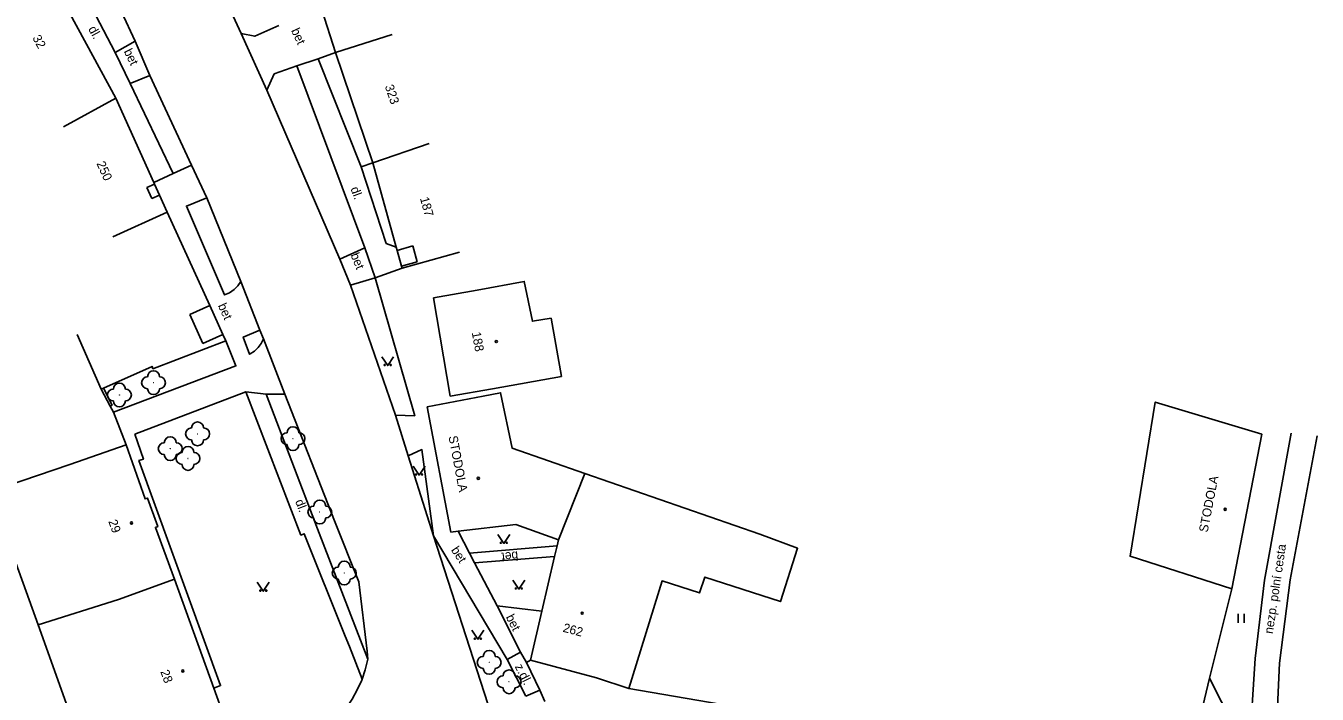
# Model space of a CAD drawing. Extents: x -544674 to -541478, y -1199076 to -1195527.
# Drawn here: x -542552 to -542443.8, y -1198856.1 to -1198800 of the extents above; entities that cross this region are included whole.
import ezdxf

# ---------------------------------------------------------------- set-up
doc = ezdxf.new("R2010")
doc.units = 0
for name, color, linetype in [('BUDOVY_MĚŘ', 7, 'Continuous'), ('BUDOVY_NEMĚŘ', 7, 'Continuous'), ('POMOC_POPIS', 7, 'Continuous'), ('ROZHRANÍ_PLOCH', 7, 'Continuous'), ('ZELEŇ', 7, 'Continuous'), ('ZN_BUDOV', 7, 'Continuous'), ('ZN_DOPLŇKOVÉ', 7, 'Continuous'), ('ZN_KULTUR', 7, 'Continuous'), ('Č_POPIS_ORIENT', 7, 'Continuous')]:
    doc.layers.add(name, color=color, linetype=linetype)

msp = doc.modelspace()

# ---------------------------------------------------------------- linework, layer by layer
at = {"layer": 'BUDOVY_MĚŘ'}
for points in [[(-542548.34, -1198798.99), (-542544.49, -1198806.08)], [(-542527.22, -1198798.68), (-542526.08, -1198802.26)], [(-542521.31, -1198800.74), (-542526.08, -1198802.26)], [(-542526.08, -1198802.26), (-542522.94, -1198811.5)], [(-542548.88, -1198808.47), (-542544.49, -1198806.08)], [(-542544.49, -1198806.08), (-542541.3, -1198813.16)], [(-542518.21, -1198809.89), (-542522.94, -1198811.5)], [(-542522.94, -1198811.5), (-542520.98, -1198818.56)], [(-542541.3, -1198813.16), (-542541.24, -1198813.29)], [(-542541.24, -1198813.29), (-542540.83, -1198814.2)], [(-542540.83, -1198814.2), (-542540.18, -1198815.64)], [(-542544.74, -1198817.7), (-542540.18, -1198815.64)], [(-542540.18, -1198815.64), (-542536.62, -1198823.47)], [(-542520.98, -1198818.56), (-542520.9, -1198818.84)], [(-542520.9, -1198818.84), (-542520.53, -1198820.17)], [(-542520.49, -1198820.33), (-542515.67, -1198818.99)], [(-542520.53, -1198820.17), (-542520.49, -1198820.33)], [(-542514.19, -1198822.18), (-542517.87, -1198822.81)], [(-542517.87, -1198822.81), (-542516.46, -1198831.07)], [(-542536.62, -1198823.47), (-542535.52, -1198825.89)], [(-542545.71, -1198830.47), (-542547.74, -1198825.9)], [(-542535.52, -1198825.89), (-542535.28, -1198826.43)], [(-542535.28, -1198826.43), (-542541.38, -1198828.77), (-542541.45, -1198828.58), (-542545.53, -1198830.39)], [(-542545.53, -1198830.39), (-542545.71, -1198830.47)], [(-542513.68, -1198831.07), (-542518.39, -1198831.96)], [(-542516.46, -1198831.07), (-542512.91, -1198830.46)], [(-542518.39, -1198831.96), (-542516.4, -1198842.46), (-542515.79, -1198842.39)], [(-542450.93, -1198847.22), (-542448.41, -1198834.25)], [(-542548.34, -1198836.8), (-542543.62, -1198835.15)], [(-542543.62, -1198835.15), (-542542.04, -1198839.68), (-542541.85, -1198839.61), (-542540.98, -1198842), (-542541.17, -1198842.07), (-542539.58, -1198846.42)], [(-542515.79, -1198842.39), (-542510.95, -1198841.84), (-542507.38, -1198843.11)], [(-542507.38, -1198843.11), (-542507.5, -1198843.61)], [(-542507.5, -1198843.61), (-542507.71, -1198844.51)], [(-542507.71, -1198844.51), (-542508.77, -1198849.09)], [(-542544.28, -1198848.13), (-542539.58, -1198846.42)], [(-542536.28, -1198855.55), (-542539.58, -1198846.42)], [(-542508.77, -1198849.09), (-542509.73, -1198853.2)], [(-542509.73, -1198853.2), (-542504.18, -1198854.68)], [(-542504.18, -1198854.68), (-542501.47, -1198855.58)], [(-542534.53, -1198860.37), (-542536.28, -1198855.55)]]:
    msp.add_lwpolyline(points, dxfattribs=at)
at = {"layer": 'BUDOVY_NEMĚŘ'}
for points in [[(-542512.91, -1198830.46), (-542507.14, -1198829.41), (-542508, -1198824.54), (-542509.57, -1198824.78), (-542510.25, -1198821.45), (-542514.19, -1198822.18)], [(-542505.18, -1198837.54), (-542511.25, -1198835.43), (-542512.23, -1198830.78), (-542513.68, -1198831.07)], [(-542448.41, -1198834.25), (-542457.34, -1198831.56), (-542459.46, -1198844.49), (-542450.93, -1198847.22)], [(-542548.34, -1198836.8), (-542555.03, -1198839.07), (-542554.8, -1198839.73), (-542556.18, -1198840.24), (-542555.02, -1198843.47), (-542553.63, -1198842.96), (-542551.01, -1198850.23)], [(-542507.38, -1198843.11), (-542505.18, -1198837.54)], [(-542505.18, -1198837.54), (-542490.49, -1198842.65), (-542487.33, -1198843.82), (-542488.77, -1198848.29), (-542495.12, -1198846.24), (-542495.55, -1198847.57), (-542498.69, -1198846.56), (-542501.47, -1198855.58)], [(-542551.01, -1198850.23), (-542544.28, -1198848.13)], [(-542551.01, -1198850.23), (-542547.26, -1198860.73), (-542543.03, -1198859.19), (-542541.43, -1198862.87)]]:
    msp.add_lwpolyline(points, dxfattribs=at)
at = {"layer": 'ROZHRANÍ_PLOCH'}
for points in [[(-542539.99, -1198787.62), (-542533.99, -1198800.65)], [(-542547.44, -1198791.44), (-542542.86, -1198801.31)], [(-542549.71, -1198792.34), (-542544.54, -1198802.24)], [(-542533.99, -1198800.65), (-542532.84, -1198800.89), (-542530.82, -1198800)], [(-542533.99, -1198800.65), (-542531.82, -1198805.4)], [(-542544.54, -1198802.24), (-542542.86, -1198801.31)], [(-542544.54, -1198802.24), (-542543.29, -1198804.86)], [(-542542.86, -1198801.31), (-542541.63, -1198804.18)], [(-542526.08, -1198802.26), (-542527.54, -1198802.77)], [(-542527.54, -1198802.77), (-542529.32, -1198803.38)], [(-542527.54, -1198802.77), (-542523.93, -1198811.84)], [(-542543.29, -1198804.86), (-542541.63, -1198804.18)], [(-542541.63, -1198804.18), (-542538.14, -1198811.69)], [(-542529.32, -1198803.38), (-542531.21, -1198804.04), (-542531.82, -1198805.4)], [(-542523.61, -1198818.63), (-542529.32, -1198803.38)], [(-542543.29, -1198804.86), (-542539.68, -1198812.41)], [(-542531.82, -1198805.4), (-542525.71, -1198819.58)], [(-542538.14, -1198811.69), (-542539.68, -1198812.41)], [(-542538.14, -1198811.69), (-542536.86, -1198814.45)], [(-542523.93, -1198811.84), (-542522.94, -1198811.5)], [(-542523.93, -1198811.84), (-542521.82, -1198818.26), (-542520.98, -1198818.56)], [(-542539.68, -1198812.41), (-542541.3, -1198813.16)], [(-542541.88, -1198813.58), (-542541.24, -1198813.29)], [(-542541.47, -1198814.49), (-542541.88, -1198813.58)], [(-542541.47, -1198814.49), (-542540.83, -1198814.2)], [(-542536.86, -1198814.45), (-542538.58, -1198815.13), (-542535.39, -1198822.58), (-542534.96, -1198822.39), (-542534.58, -1198822.13), (-542534.26, -1198821.82), (-542534, -1198821.45)], [(-542536.86, -1198814.45), (-542534, -1198821.45)], [(-542520.9, -1198818.84), (-542519.59, -1198818.47)], [(-542519.59, -1198818.47), (-542519.22, -1198819.8)], [(-542523.61, -1198818.63), (-542525.71, -1198819.58)], [(-542525.71, -1198819.58), (-542524.81, -1198821.77)], [(-542522.74, -1198821.14), (-542523.61, -1198818.63)], [(-542520.49, -1198820.33), (-542522.74, -1198821.14)], [(-542520.53, -1198820.17), (-542519.22, -1198819.8)], [(-542534, -1198821.45), (-542532.41, -1198825.53)], [(-542524.81, -1198821.77), (-542522.74, -1198821.14)], [(-542521.03, -1198832.67), (-542519.43, -1198832.71), (-542522.74, -1198821.14)], [(-542524.81, -1198821.77), (-542521.03, -1198832.67)], [(-542538.3, -1198824.23), (-542536.62, -1198823.47)], [(-542537.2, -1198826.65), (-542538.3, -1198824.23)], [(-542537.2, -1198826.65), (-542535.52, -1198825.89)], [(-542532.41, -1198825.53), (-542533.81, -1198826.12), (-542533.28, -1198827.55), (-542533.23, -1198827.53), (-542532.87, -1198827.3), (-542532.56, -1198827), (-542532.31, -1198826.66), (-542532.12, -1198826.27)], [(-542532.41, -1198825.53), (-542532.12, -1198826.27)], [(-542535.28, -1198826.43), (-542534.43, -1198828.53), (-542544.68, -1198832.41)], [(-542532.12, -1198826.27), (-542530.31, -1198830.9)], [(-542533.58, -1198830.7), (-542542.91, -1198834.26)], [(-542533.58, -1198830.7), (-542531.88, -1198830.91)], [(-542533.58, -1198830.7), (-542528.97, -1198842.71), (-542528.69, -1198842.6), (-542525.27, -1198851.19), (-542524.89, -1198852.07), (-542523.85, -1198854.79)], [(-542530.31, -1198830.9), (-542531.88, -1198830.91)], [(-542531.88, -1198830.91), (-542527.59, -1198842.18), (-542523.36, -1198853.11)], [(-542530.31, -1198830.9), (-542526.17, -1198841.53), (-542524.12, -1198846.63)], [(-542544.68, -1198832.41), (-542544.98, -1198831.9)], [(-542521.03, -1198832.67), (-542519.99, -1198836.08)], [(-542542.91, -1198834.26), (-542542.18, -1198836.34), (-542542.56, -1198836.47), (-542535.71, -1198855.34), (-542536.28, -1198855.55)], [(-542445.96, -1198834.18), (-542448.2, -1198846.5), (-542448.97, -1198853.07), (-542449.45, -1198860.45), (-542449.85, -1198863.37), (-542450.69, -1198865.58), (-542451.64, -1198867.29), (-542453.03, -1198868.4), (-542453.67, -1198868.75), (-542455.26, -1198869.34)], [(-542449.61, -1198870.92), (-542449.06, -1198868.38), (-542447.68, -1198864.24), (-542447.25, -1198860.78), (-542446.93, -1198853.47), (-542446.03, -1198846.48), (-542443.77, -1198834.39)], [(-542519.99, -1198836.08), (-542518.83, -1198835.55), (-542517.86, -1198842.77)], [(-542519.99, -1198836.08), (-542517.86, -1198842.77)], [(-542517.86, -1198842.77), (-542513.3, -1198856.86)], [(-542517.86, -1198842.77), (-542511.68, -1198853.16)], [(-542515.79, -1198842.39), (-542514.84, -1198844.22)], [(-542507.5, -1198843.61), (-542514.84, -1198844.22)], [(-542514.84, -1198844.22), (-542514.41, -1198845.04)], [(-542507.71, -1198844.51), (-542514.41, -1198845.04)], [(-542514.41, -1198845.04), (-542512.53, -1198848.65)], [(-542524.12, -1198846.63), (-542523.43, -1198852.44)], [(-542512.53, -1198848.65), (-542510.56, -1198852.53)], [(-542512.53, -1198848.65), (-542508.77, -1198849.09)], [(-542523.36, -1198853.11), (-542523.59, -1198854.02), (-542523.85, -1198854.79)], [(-542523.43, -1198852.44), (-542523.36, -1198853.11)], [(-542510.56, -1198852.53), (-542511.68, -1198853.16)], [(-542510.56, -1198852.53), (-542510.07, -1198853.41)], [(-542511.68, -1198853.16), (-542510.13, -1198856.23)], [(-542510.07, -1198853.41), (-542509.73, -1198853.2)], [(-542508.95, -1198855.72), (-542510.07, -1198853.41)], [(-542523.85, -1198854.79), (-542523.88, -1198854.87), (-542524.25, -1198855.69), (-542524.69, -1198856.48), (-542525.19, -1198857.22), (-542525.66, -1198857.79), (-542526.81, -1198859.02), (-542528.01, -1198860.19), (-542529.27, -1198861.3), (-542530.58, -1198862.35), (-542531.94, -1198863.33), (-542532.56, -1198863.75), (-542535.73, -1198865.15)], [(-542510.13, -1198856.23), (-542508.95, -1198855.72)], [(-542508.95, -1198855.72), (-542508.52, -1198856.67)]]:
    msp.add_lwpolyline(points, dxfattribs=at)
at = {"layer": 'ZELEŇ'}
msp.add_lwpolyline([(-542455.55, -1198866.21), (-542453.49, -1198867.42), (-542451.08, -1198863.87), (-542450.79, -1198858.67), (-542452.79, -1198854.71)], dxfattribs=at)
for centre in [(-542541.33, -1198829.94), (-542544.19, -1198830.97), (-542537.64, -1198834.23), (-542529.64, -1198834.63), (-542539.93, -1198835.47), (-542538.44, -1198836.29), (-542527.39, -1198840.78), (-542525.34, -1198845.9), (-542513.19, -1198853.39), (-542511.52, -1198855.02)]:
    msp.add_circle(centre, 0.0005, dxfattribs=at)
for centre, start, end in [((-542541.33, -1198829.44), 0, 179.99999), ((-542544.19, -1198830.47), 0, 179.99999), ((-542541.83, -1198829.94), 89.99999, 269.99999), ((-542540.83, -1198829.94), 270, 89.99999), ((-542544.69, -1198830.97), 89.99999, 269.99999), ((-542544.19, -1198831.47), 179.99999, 359.99999), ((-542543.69, -1198830.97), 270, 89.99999), ((-542541.33, -1198830.44), 179.99999, 359.99999), ((-542537.64, -1198833.73), 0, 179.99999), ((-542529.64, -1198834.13), 0, 179.99999), ((-542539.93, -1198834.97), 0, 179.99999), ((-542538.14, -1198834.23), 89.99999, 269.99999), ((-542537.64, -1198834.73), 179.99999, 359.99999), ((-542537.14, -1198834.23), 270, 89.99999), ((-542530.14, -1198834.63), 89.99999, 269.99999), ((-542529.14, -1198834.63), 270, 89.99999), ((-542540.43, -1198835.47), 89.99999, 269.99999), ((-542538.94, -1198836.29), 89.99999, 269.99999), ((-542539.43, -1198835.47), 270, 89.99999), ((-542538.44, -1198835.79), 0, 179.99999), ((-542537.94, -1198836.29), 270, 89.99999), ((-542529.64, -1198835.13), 179.99999, 359.99999), ((-542539.93, -1198835.97), 179.99999, 359.99999), ((-542538.44, -1198836.79), 179.99999, 359.99999), ((-542527.39, -1198840.28), 0, 179.99999), ((-542527.89, -1198840.78), 89.99999, 269.99999), ((-542526.89, -1198840.78), 270, 89.99999), ((-542527.39, -1198841.28), 179.99999, 359.99999), ((-542525.84, -1198845.9), 89.99999, 269.99999), ((-542525.34, -1198845.4), 0, 179.99999), ((-542524.84, -1198845.9), 270, 89.99999), ((-542525.34, -1198846.4), 179.99999, 359.99999), ((-542513.69, -1198853.39), 89.99999, 269.99999), ((-542513.19, -1198852.89), 0, 179.99999), ((-542512.69, -1198853.39), 270, 89.99999), ((-542513.19, -1198853.89), 179.99999, 359.99999), ((-542511.52, -1198854.52), 0, 179.99999), ((-542512.02, -1198855.02), 89.99999, 269.99999), ((-542511.02, -1198855.02), 270, 89.99999), ((-542511.52, -1198855.52), 179.99999, 359.99999)]:
    msp.add_arc(centre, 0.5, start, end, dxfattribs=at)
at = {"layer": 'ZN_BUDOV'}
for centre in [(-542512.59, -1198826.49), (-542514.1, -1198837.96), (-542451.48, -1198840.56), (-542543.18, -1198841.7), (-542505.39, -1198849.27), (-542538.88, -1198854.11)]:
    msp.add_circle(centre, 0.0875, dxfattribs=at)
at = {"layer": 'ZN_DOPLŇKOVÉ'}
for points in [[(-542544.98, -1198831.9), (-542544.8, -1198831.81), (-542545.53, -1198830.39)], [(-542545.71, -1198830.47), (-542544.98, -1198831.9)], [(-542543.62, -1198835.15), (-542544.68, -1198832.41)], [(-542452.79, -1198854.71), (-542450.93, -1198847.22)], [(-542455.55, -1198866.21), (-542452.79, -1198854.71)], [(-542501.47, -1198855.58), (-542491.87, -1198857.22), (-542485.78, -1198858.25)]]:
    msp.add_lwpolyline(points, dxfattribs=at)
at = {"layer": 'ZN_KULTUR'}
for p, q in [((-542450.38, -1198850.065), (-542450.38, -1198849.315)), ((-542449.88, -1198850.065), (-542449.88, -1198849.315))]:
    msp.add_line(p, q, dxfattribs=at)
for points in [[(-542522.2, -1198827.76), (-542521.7, -1198828.51), (-542521.2, -1198827.76)], [(-542519.56, -1198836.94), (-542519.06, -1198837.69), (-542518.56, -1198836.94)], [(-542512.46, -1198842.66), (-542511.96, -1198843.41), (-542511.46, -1198842.66)], [(-542511.2, -1198846.49), (-542510.7, -1198847.24), (-542510.2, -1198846.49)], [(-542532.63, -1198846.67), (-542532.13, -1198847.42), (-542531.63, -1198846.67)], [(-542514.64, -1198850.7), (-542514.14, -1198851.45), (-542513.64, -1198850.7)]]:
    msp.add_lwpolyline(points, dxfattribs=at)
for centre in [(-542521.95, -1198828.46), (-542521.45, -1198828.46), (-542519.31, -1198837.64), (-542518.81, -1198837.64), (-542512.21, -1198843.36), (-542511.71, -1198843.36), (-542532.38, -1198847.37), (-542531.88, -1198847.37), (-542510.95, -1198847.19), (-542510.45, -1198847.19), (-542514.39, -1198851.4), (-542513.89, -1198851.4)]:
    msp.add_circle(centre, 0.05, dxfattribs=at)

# ---------------------------------------------------------------- texts
at = {"layer": 'POMOC_POPIS'}
for s, rotation, p in [('dl.', 298.50998, (-542546.83, -1198800.27)), ('bet', 294.54998, (-542529.81, -1198800.4)), ('bet', 296.57, (-542543.85, -1198802.16)), ('dl.', 290.53, (-542524.83, -1198813.66)), ('bet', 292.34003, (-542524.83, -1198819.22)), ('bet', 294.41998, (-542535.95, -1198823.47)), ('STODOLA', 280.67999, (-542516.6, -1198834.45)), ('STODOLA', 78.99999, (-542452.96, -1198842.53)), ('dl.', 290.99999, (-542529.47, -1198839.88)), ('bet', 303.73003, (-542516.42, -1198843.97)), ('bet', 184.79997, (-542510.79, -1198844.08)), ('nezp. polní cesta', 81.51001, (-542447.49, -1198851.03)), ('bet', 297.34, (-542511.82, -1198849.59)), ('z.dl.', 296.79002, (-542511.06, -1198853.73))]:
    msp.add_text(s, height=0.75, rotation=rotation, dxfattribs=at).set_placement(p)
at = {"layer": 'Č_POPIS_ORIENT'}
for s, rotation, p in [('32', 298.50998, (-542551.51, -1198801.02)), ('323', 288.76998, (-542521.95, -1198805.08)), ('250', 294.26998, (-542546.13, -1198811.56)), ('187', 285.51003, (-542519, -1198814.47)), ('188', 280.47, (-542514.65, -1198825.74)), ('29', 290.00001, (-542545.13, -1198841.57)), ('262', 345.07002, (-542507.06, -1198850.81)), ('28', 289.90003, (-542540.77, -1198854.16))]:
    msp.add_text(s, height=0.75, rotation=rotation, dxfattribs=at).set_placement(p)

doc.saveas('drawing.dxf')
